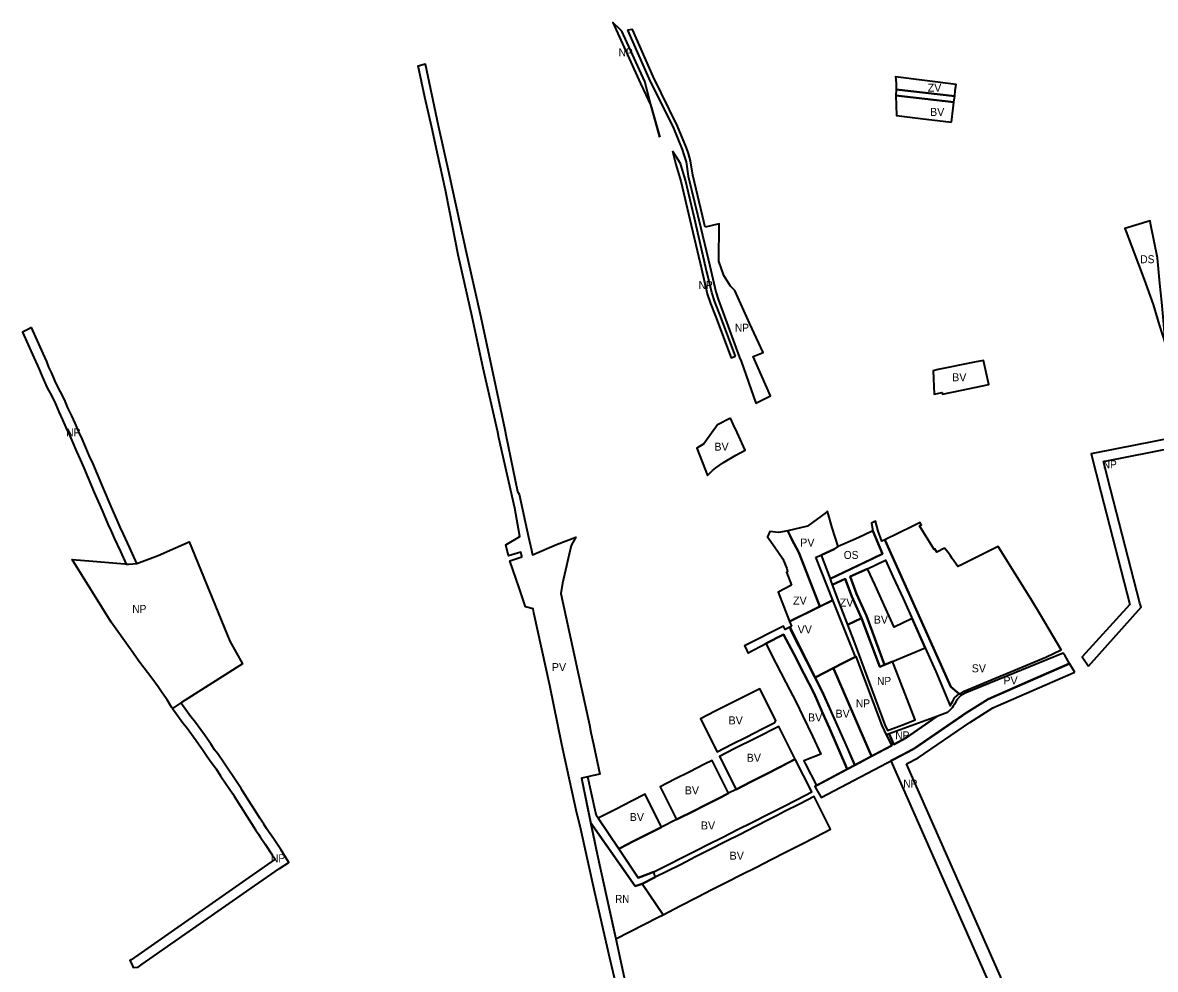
# Model space of a CAD drawing. Extents: x -650276 to -642489, y -1074311 to -1066658.
# Drawn here: x -649558 to -647860, y -1068079 to -1066658 of the extents above; entities that cross this region are included whole.
import ezdxf

# ---------------------------------------------------------------- set-up
doc = ezdxf.new("R2010")
doc.units = 0
doc.header["$LTSCALE"] = 4.8
for name, color, linetype, lineweight in [('15', 7, 'Continuous', 35), ('18', 7, 'Continuous', 35), ('24', 7, 'Continuous', 35), ('3', 7, 'Continuous', 35), ('40', 7, 'Continuous', 35), ('45', 7, 'Continuous', 35), ('48', 7, 'Continuous', 35), ('7', 7, 'Continuous', 35), ('9', 7, 'Continuous', 35)]:
    doc.layers.add(name, color=color, linetype=linetype, lineweight=lineweight)
doc.layers.add('62', color=7, linetype='Continuous')
doc.layers.add('63', color=7, linetype='Continuous')

msp = doc.modelspace()

# ---------------------------------------------------------------- linework, layer by layer
at = {"layer": '15'}
for points in [[(-648662.71, -1068124.76), (-648677.61, -1068061.74), (-648700.16, -1067963.42), (-648722.09, -1067863.84), (-648727.05, -1067844.33), (-648738.7, -1067792.04), (-648749.97, -1067741.49), (-648767.84, -1067652.98), (-648791.68, -1067543.78), (-648792.97, -1067537.86), (-648804.08, -1067534.88), (-648813.94, -1067506.27), (-648827.86, -1067465.86), (-648809.65, -1067459.77), (-648809.97, -1067458.52), (-648811.21, -1067453.52), (-648811.4, -1067452.79), (-648829.54, -1067458.42), (-648834.01, -1067441.81), (-648812.91, -1067429.16), (-648820.39, -1067386.83), (-648844.16, -1067281.37), (-648845.94, -1067272.85), (-648867.82, -1067176.66), (-648884.26, -1067099.63), (-648899.1, -1067033.34), (-648905.06, -1067006.7), (-648917.76, -1066942.65), (-648924.32, -1066909.55), (-648936.7, -1066852.52), (-648944.75, -1066815.41), (-648955.15, -1066770.11), (-648965.39, -1066723.15), (-648959.88, -1066721.59), (-648954.86, -1066720.16), (-648935.19, -1066812.53), (-648918.27, -1066888.41), (-648914.11, -1066907.05), (-648893.02, -1067002.5), (-648872.31, -1067095.5), (-648851.87, -1067191.04), (-648835.29, -1067268.93), (-648833.66, -1067276.77), (-648816.06, -1067361.71), (-648813.81, -1067365.91), (-648799.58, -1067430.4), (-648796.8, -1067443.1), (-648795.88, -1067447.21), (-648794.7, -1067452.46), (-648793.71, -1067456.88), (-648757.97, -1067441.51), (-648728.95, -1067430.33), (-648735.59, -1067442.88), (-648748.53, -1067499.3), (-648751.29, -1067514.57), (-648731.06, -1067607.06), (-648725.8, -1067632.36), (-648720.1, -1067657.12), (-648708.26, -1067712.07), (-648706.08, -1067723.56), (-648702.33, -1067740.84), (-648692.53, -1067785.79), (-648704.614, -1067788.491), (-648710.961, -1067789.906), (-648720.34, -1067792), (-648696.93, -1067905.76), (-648672.31, -1068017.25), (-648668.92, -1068032.96), (-648651.89, -1068111.95)], [(-648710.961, -1067789.906), (-648720.34, -1067792), (-648706.687, -1067858.345), (-648640, -1067954)], [(-648695.27, -1067852.04), (-648697.7, -1067848.43), (-648699.621, -1067840.06), (-648699.593, -1067840.046), (-648710.96, -1067789.91)], [(-648611.61, -1067932.63), (-648620.658, -1067935.93), (-648635.249, -1067941.252), (-648664.41, -1067897.91), (-648695.27, -1067852.04)], [(-648640, -1067954), (-648629.22, -1067950.214), (-648609.91, -1067940.58), (-648611.61, -1067932.63)]]:
    msp.add_lwpolyline(points, dxfattribs=at)
for points in [[(-648161.58, -1066777.41), (-648160.51, -1066768.4), (-648248.43, -1066758.34), (-648248.77, -1066767.43)], [(-648369.01, -1067460.52), (-648361, -1067457.36), (-648341.15, -1067448.14), (-648335.38, -1067444.07), (-648344.41, -1067416.04), (-648349.67, -1067396.88), (-648351.06, -1067391.62), (-648352.16, -1067392.42), (-648353.35, -1067393.29), (-648381.48, -1067413.68), (-648410.92, -1067420.63), (-648409.61, -1067423.44), (-648404.29, -1067434.9), (-648394.92, -1067452.23), (-648393.17, -1067455.88), (-648362.585, -1067534.205), (-648343.41, -1067524.81), (-648369.01, -1067460.52)], [(-648237.81, -1067522.42), (-648204.88, -1067596.54), (-648198.39, -1067610.97), (-648193.8, -1067621), (-648189.03, -1067631.71), (-648167.48, -1067683.45), (-648164.79, -1067678.96), (-648163.11, -1067676.17), (-648160.68, -1067671.55), (-648153.98, -1067665.43), (-648166.173, -1067654.853), (-648240.51, -1067489.9), (-648265.197, -1067434.03), (-648265.197, -1067434.03), (-648270.02, -1067436.37), (-648275.41, -1067421.3), (-648279.24, -1067406.38), (-648285.08, -1067409.24), (-648283.21, -1067420.88), (-648268.67, -1067455.43), (-648297.915, -1067469.319), (-648326.09, -1067482.7), (-648347.51, -1067492.87), (-648346.27, -1067496.14), (-648344.186, -1067501.627), (-648324.735, -1067492.8), (-648314.647, -1067519.171), (-648300.258, -1067551.772), (-648299.23, -1067554.52), (-648272.941, -1067624.811), (-648265.601, -1067621.762), (-648292.991, -1067548.356), (-648307.57, -1067515.44), (-648317.435, -1067489.488), (-648291.172, -1067477.571), (-648264.34, -1067464.83), (-648253.1, -1067489.23)], [(-648359.6, -1067691.58), (-648348.55, -1067716.71), (-648337.32, -1067742.59), (-648326, -1067769), (-648321.623, -1067778.399), (-648310.511, -1067772.476), (-648323.178, -1067741.953), (-648359.213, -1067661.956), (-648405.054, -1067571.837), (-648408.002, -1067565.219), (-648414.73, -1067568.8), (-648417.19, -1067564.02), (-648475.78, -1067593.11), (-648473.34, -1067598.06), (-648470.57, -1067603.69), (-648470.47, -1067603.64), (-648443.83, -1067589.92), (-648417.12, -1067576.17), (-648402.02, -1067605.49), (-648386.91, -1067634.83), (-648371.34, -1067665.08)], [(-647988.235, -1067619.912), (-647995.04, -1067608.56), (-647997.68, -1067604.11), (-648144.83, -1067664.48), (-648151.6, -1067668.12), (-648157.2, -1067674.32), (-648161, -1067680.96), (-648162.69, -1067684), (-648164.09, -1067686.51), (-648171.21, -1067693.37), (-648187.139, -1067699.179), (-648233.264, -1067731.288), (-648251.711, -1067741.124), (-648258.96, -1067725.37), (-648262.632, -1067726.711), (-648255.016, -1067742.886), (-648319.983, -1067777.526), (-648370.113, -1067804.22), (-648360.993, -1067821.027), (-648222.872, -1067748.412), (-648146.127, -1067695.8), (-648110.36, -1067673.133), (-647988.052, -1067619.624)]]:
    msp.add_lwpolyline(points, close=True, dxfattribs=at)
at = {"layer": '18'}
msp.add_lwpolyline([(-648153.98, -1067665.43), (-648149.933, -1067663.646), (-648146.21, -1067661.3), (-648023.96, -1067610.13), (-648000.63, -1067599.14), (-648031.77, -1067546.6), (-648045.04, -1067525.15), (-648076.32, -1067474.6), (-648081.31, -1067466.54), (-648095.28, -1067444.06), (-648133.56, -1067463.2), (-648150.46, -1067471.66), (-648155.85, -1067474.35), (-648164.24, -1067462.15), (-648166.97, -1067458.18), (-648170.38, -1067453.23), (-648175.94, -1067446.89), (-648187.44, -1067452.8), (-648190.23, -1067447.83), (-648191.46, -1067448.59), (-648213.34, -1067413.46), (-648210.48, -1067411.68), (-648211.08, -1067410.6), (-648212.32, -1067408.39), (-648224.19, -1067414.14), (-648265.197, -1067434.03), (-648240.51, -1067489.9), (-648240.51, -1067489.9), (-648166.173, -1067654.853)], close=True, dxfattribs=at)
at = {"layer": '24'}
msp.add_lwpolyline([(-647876.57, -1067043.5), (-647863.04, -1067081.36), (-647853.65, -1067111.91), (-647844.3, -1067141.25), (-647847.09, -1067110.58), (-647850.07, -1067077.71), (-647852.63, -1067049.52), (-647856.11, -1067011.21), (-647866.14, -1066961.98), (-647867.46, -1066955.52), (-647905.28, -1066967.07), (-647903.5, -1066972.05)], close=True, dxfattribs=at)
at = {"layer": '3'}
for points in [[(-648165.33, -1066807.74), (-648162.8, -1066786.8), (-648161.58, -1066777.41), (-648248.77, -1066767.43), (-648247.78, -1066797.53), (-648211.58, -1066802.18)], [(-648185.185, -1067178.687), (-648193.02, -1067180.66), (-648191.44, -1067215.62), (-648179.42, -1067213.37), (-648179, -1067215.71), (-648152.5, -1067210.23), (-648109.1, -1067201.21), (-648117.562, -1067165.197), (-648131.01, -1067167.84)], [(-648496.55, -1067251.53), (-648516.47, -1067261.54), (-648536.84, -1067290.29), (-648547.17, -1067296.68), (-648531.51, -1067337.57), (-648523.55, -1067330.33), (-648518.55, -1067326.3), (-648507.25, -1067318.35), (-648488.66, -1067307.11), (-648474.69, -1067299.66), (-648486.79, -1067273.26), (-648492.62, -1067260.53)], [(-648263.7, -1067537.93), (-648279.86, -1067502.11), (-648291.17, -1067477.57), (-648317.435, -1067489.488), (-648307.57, -1067515.44), (-648292.991, -1067548.356), (-648265.601, -1067621.762), (-648254.04, -1067616.96), (-648254.04, -1067616.96), (-648204.88, -1067596.54), (-648224.16, -1067552.55), (-648251.33, -1067565.28)], [(-648397.98, -1067678.79), (-648388.526, -1067698.603), (-648373.99, -1067728.95), (-648361.08, -1067755.88), (-648387.04, -1067765.67), (-648384.25, -1067771.07), (-648367.811, -1067802.994), (-648321.623, -1067778.399), (-648326, -1067769), (-648337.32, -1067742.59), (-648348.55, -1067716.71), (-648359.6, -1067691.58), (-648371.34, -1067665.08), (-648386.91, -1067634.83), (-648402.02, -1067605.49), (-648417.12, -1067576.17), (-648443.83, -1067589.92), (-648428.7, -1067619.24), (-648413.57, -1067648.57)], [(-648342.697, -1067626.806), (-648369.949, -1067640.851), (-648359.213, -1067661.956), (-648310.511, -1067772.476), (-648285.254, -1067759.008), (-648296.891, -1067732.172), (-648342.023, -1067628.096)], [(-648519.63, -1067691.58), (-648541.86, -1067702.86), (-648516.73, -1067752.57), (-648494.84, -1067741.06), (-648472.5, -1067729.76), (-648450.23, -1067718.32), (-648430.17, -1067708.33), (-648428.67, -1067705.52), (-648452.72, -1067657.62)], [(-648491.14, -1067748.02), (-648513.23, -1067759.38), (-648488.49, -1067808.76), (-648466.36, -1067797.5), (-648455.32, -1067791.85), (-648444.28, -1067786.19), (-648421.84, -1067774.66), (-648410.78, -1067768.98), (-648399.64, -1067763.26), (-648424.14, -1067714.34), (-648435.34, -1067720.01), (-648446.58, -1067725.71), (-648468.97, -1067736.91), (-648480.06, -1067742.47)], [(-648577.78, -1067854.07), (-648571.69, -1067851.06), (-648555.32, -1067842.99), (-648532.98, -1067831.54), (-648510.82, -1067820.19), (-648499.7, -1067814.37), (-648524.44, -1067765.11), (-648535.61, -1067770.85), (-648557.84, -1067782.26), (-648580.14, -1067793.61), (-648602.3, -1067804.83)], [(-648644.095, -1067887.6), (-648620.51, -1067875.63), (-648600.14, -1067865.29), (-648624.76, -1067816.11), (-648645.11, -1067826.48), (-648668.085, -1067838.186), (-648675.26, -1067841.84), (-648695.27, -1067852.04), (-648664.41, -1067897.91), (-648650.68, -1067890.94)]]:
    msp.add_lwpolyline(points, close=True, dxfattribs=at)
for points in [[(-648611.61, -1067932.63), (-648611.61, -1067932.63), (-648547.09, -1067899.87), (-648530.81, -1067891.61), (-648508.22, -1067880.38), (-648486.09, -1067868.98), (-648463.91, -1067857.74), (-648441.47, -1067846.37), (-648419.44, -1067835.3), (-648397.04, -1067823.85), (-648374.84, -1067812.43), (-648399.64, -1067763.26), (-648421.84, -1067774.66)], [(-648421.84, -1067774.66), (-648444.28, -1067786.19), (-648455.32, -1067791.85), (-648466.36, -1067797.5), (-648488.49, -1067808.76)], [(-648572.5, -1067983.59), (-648546.76, -1067970.44), (-648524.72, -1067958.93), (-648502.59, -1067948), (-648480.12, -1067936.55), (-648457.87, -1067925.4), (-648435.55, -1067913.84), (-648413.41, -1067902.53), (-648402.29, -1067897.02), (-648391.08, -1067891.24), (-648368.78, -1067879.75), (-648346.57, -1067868.56), (-648371.27, -1067819.47), (-648393.35, -1067830.81), (-648415.69, -1067841.98), (-648426.65, -1067847.64), (-648437.89, -1067853.4), (-648460.33, -1067864.88), (-648482.5, -1067876.22), (-648504.92, -1067887.52), (-648527.33, -1067898.74), (-648549.44, -1067910.07), (-648571.88, -1067921.71), (-648591.04, -1067931.62), (-648609.91, -1067940.58)], [(-648488.49, -1067808.76), (-648499.7, -1067814.37), (-648510.82, -1067820.19), (-648532.98, -1067831.54), (-648555.32, -1067842.99), (-648571.69, -1067851.06)], [(-648571.69, -1067851.06), (-648577.78, -1067854.07), (-648600.14, -1067865.29)], [(-648600.14, -1067865.29), (-648620.51, -1067875.63), (-648644.095, -1067887.6)], [(-648644.095, -1067887.6), (-648650.68, -1067890.94), (-648664.41, -1067897.91), (-648635.249, -1067941.252), (-648620.658, -1067935.93), (-648611.61, -1067932.63)], [(-648609.91, -1067940.58), (-648629.22, -1067950.214), (-648597.93, -1067996.72), (-648572.5, -1067983.59)]]:
    msp.add_lwpolyline(points, dxfattribs=at)
at = {"layer": '40'}
for points in [[(-648160.51, -1066768.4), (-648159.66, -1066759.8), (-648158.49, -1066750.93), (-648249.44, -1066739.8), (-648248.34, -1066749.33), (-648248.43, -1066758.34)], [(-648405.27, -1067502.27), (-648425.5, -1067512.73), (-648408.26, -1067556.58), (-648362.585, -1067534.205), (-648393.17, -1067455.88), (-648394.92, -1067452.23), (-648404.29, -1067434.9), (-648410.92, -1067420.63), (-648425, -1067423.05), (-648437.75, -1067421.99), (-648441.48, -1067429.63), (-648430.4, -1067445.51), (-648418.3, -1067462.86), (-648412.46, -1067477.42), (-648411.25, -1067481.73), (-648412.89, -1067482.55)], [(-648324.735, -1067492.8), (-648344.186, -1067501.627), (-648334.09, -1067528.2), (-648321.36, -1067561.69), (-648300.258, -1067551.772), (-648314.647, -1067519.171)]]:
    msp.add_lwpolyline(points, close=True, dxfattribs=at)
for points in [[(-648314.647, -1067519.171), (-648324.735, -1067492.8), (-648344.186, -1067501.627)], [(-648344.186, -1067501.627), (-648334.09, -1067528.2), (-648321.36, -1067561.69)], [(-648321.36, -1067561.69), (-648300.258, -1067551.772), (-648314.647, -1067519.171)]]:
    msp.add_lwpolyline(points, dxfattribs=at)
at = {"layer": '45'}
msp.add_lwpolyline([(-648405.41, -1067563.84), (-648408.002, -1067565.219), (-648369.949, -1067640.851), (-648342.697, -1067626.806), (-648328.54, -1067619.51), (-648309.522, -1067609.713), (-648317.43, -1067590), (-648343.41, -1067524.81), (-648408.26, -1067556.58)], close=True, dxfattribs=at)
at = {"layer": '48'}
for points in [[(-648602.97, -1066830.11), (-648616.86, -1066779.79), (-648625.44, -1066746.45), (-648659.95, -1066670.89), (-648662.46, -1066668.53), (-648673.407, -1066658.275), (-648631.791, -1066749.394)], [(-648534.701, -1066965.077), (-648538.812, -1066947.891), (-648553.323, -1066887.238), (-648556.637, -1066865.397), (-648559.94, -1066854.66), (-648562.542, -1066846.219), (-648576.145, -1066813.802), (-648612.763, -1066739.165), (-648643.925, -1066668.483), (-648651.042, -1066669.551), (-648651.1, -1066669.56)], [(-648651.1, -1066669.56), (-648619.11, -1066742.12), (-648582.52, -1066816.7)], [(-648631.791, -1066749.394), (-648616.104, -1066782.727), (-648602.97, -1066830.11)], [(-648582.52, -1066816.7), (-648569.13, -1066848.61), (-648566.63, -1066856.72), (-648563.48, -1066866.96), (-648560.2, -1066888.58), (-648541.521, -1066966.657), (-648541.52, -1066966.657)], [(-648571.96, -1066869.37), (-648577.99, -1066860.17), (-648583.94, -1066851.11)], [(-648583.94, -1066851.11), (-648578.702, -1066871.259), (-648571.167, -1066896.326), (-648557.816, -1066953.444)], [(-648489.1, -1067158.84), (-648512.95, -1067095.97), (-648520.4, -1067077.42), (-648524.93, -1067063.35), (-648533.66, -1067026), (-648551, -1066951.85), (-648564.4, -1066894.52), (-648571.96, -1066869.37)], [(-648557.816, -1066953.444), (-648540.476, -1067027.594), (-648531.681, -1067065.222)], [(-648541.52, -1066966.657), (-648528.01, -1067023.13), (-648518.72, -1067061.99), (-648514.86, -1067074.83), (-648507.88, -1067093.9), (-648483.31, -1067160.63), (-648480.57, -1067166.13), (-648458.73, -1067229.1), (-648449.03, -1067224.14), (-648437.02, -1067217.99), (-648462.97, -1067159.24), (-648447.66, -1067153.25), (-648467.56, -1067110.02), (-648490.23, -1067060.06), (-648496.87, -1067053.5), (-648506.78, -1067037.81), (-648514.38, -1067016.2), (-648513.842, -1066960.243), (-648534.701, -1066965.077)], [(-648531.681, -1067065.222), (-648526.988, -1067079.8), (-648519.471, -1067098.516), (-648495.644, -1067161.326), (-648489.1, -1067158.84)], [(-647882.66, -1067529.231), (-647926.759, -1067358.379), (-647937.355, -1067316.774), (-647828.376, -1067295.406), (-647828.104, -1067295.352), (-647831.28, -1067280.69), (-647948.488, -1067303.671)], [(-647948.488, -1067303.671), (-647955.805, -1067305.106), (-647941.289, -1067362.104)], [(-647941.289, -1067362.104), (-647897.637, -1067531.223), (-647969.29, -1067609.79), (-647959.832, -1067623.65)], [(-647959.832, -1067623.65), (-647881.085, -1067535.333), (-647882.66, -1067529.231)], [(-648254.04, -1067616.96), (-648272.941, -1067624.811), (-648300.258, -1067551.772), (-648321.36, -1067561.69)], [(-648321.36, -1067561.69), (-648311.95, -1067586.45), (-648265.08, -1067712.06)], [(-648265.08, -1067712.06), (-648261.25, -1067720.39), (-648235.78, -1067710.79), (-648219.86, -1067704.42), (-648247.53, -1067633.53), (-648254.04, -1067616.96)], [(-648095.475, -1067682.994), (-647983.06, -1067633.813), (-647980.561, -1067632.719)], [(-647980.561, -1067632.719), (-647982.95, -1067628.73), (-647988.334, -1067619.747), (-648046.773, -1067645.314)], [(-648046.773, -1067645.314), (-648110.36, -1067673.133), (-648146.127, -1067695.8), (-648146.146, -1067695.813), (-648149.529, -1067698.132), (-648222.53, -1067748.178)], [(-648232.676, -1067770.513), (-648215.115, -1067761.28), (-648137.869, -1067708.325), (-648114.323, -1067693.403), (-648103.298, -1067686.416), (-648095.475, -1067682.994)], [(-648222.53, -1067748.178), (-648222.872, -1067748.412), (-648238.748, -1067756.759)], [(-648238.748, -1067756.759), (-648256.499, -1067766.091), (-648079.002, -1068168.139)], [(-648079.002, -1068168.139), (-648061.329, -1068158.649), (-648232.676, -1067770.513)]]:
    msp.add_lwpolyline(points, dxfattribs=at)
for points in [[(-649545.203, -1067115.647), (-649549.7, -1067118.05), (-649558.469, -1067122.73), (-649541.537, -1067160.722), (-649536.075, -1067172.622), (-649532.831, -1067180.855), (-649529.013, -1067189.389), (-649521.663, -1067206.124), (-649514.869, -1067218.957), (-649509.44, -1067230.141), (-649504.224, -1067242.225), (-649498.572, -1067254.427), (-649493.526, -1067265.611), (-649487.812, -1067278.312), (-649482.963, -1067288.934), (-649477.677, -1067301.655), (-649472.327, -1067313.644), (-649466.703, -1067326.24), (-649451.059, -1067363.074), (-649439.265, -1067390.397), (-649430.531, -1067410.689), (-649425.804, -1067421.21), (-649421.071, -1067431.944), (-649411.913, -1067451.746), (-649403.34, -1067470.579), (-649399.39, -1067470.93), (-649387.4, -1067469.98), (-649387.17, -1067469.894), (-649398.28, -1067445.49), (-649407.4, -1067425.77), (-649412.1, -1067415.11), (-649416.8, -1067404.65), (-649425.49, -1067384.46), (-649437.27, -1067357.17), (-649452.95, -1067320.25), (-649458.63, -1067307.53), (-649463.9, -1067295.72), (-649469.21, -1067282.94), (-649474.15, -1067272.12), (-649479.85, -1067259.45), (-649484.93, -1067248.19), (-649490.53, -1067236.1), (-649495.8, -1067223.89), (-649501.49, -1067212.17), (-649508.15, -1067199.59), (-649515.3, -1067183.31), (-649519, -1067175.04), (-649522.27, -1067166.74), (-649527.87, -1067154.54)], [(-649333.74, -1067687.4), (-649335.26, -1067685.21), (-649341.81, -1067674.33), (-649349.12, -1067663.84), (-649355.46, -1067654.85), (-649364.69, -1067641.98), (-649382.53, -1067618.33), (-649391.04, -1067606.27), (-649393.23, -1067603.28), (-649425.69, -1067557.7), (-649484.28, -1067463.88), (-649453.39, -1067466.13), (-649399.39, -1067470.93), (-649387.4, -1067469.98), (-649355.44, -1067457.94), (-649329.068, -1067446.175), (-649308.75, -1067437.11), (-649247.518, -1067586.255), (-649228.52, -1067620.294), (-649320.47, -1067678.44)], [(-648342.023, -1067628.096), (-648296.891, -1067732.172), (-648285.254, -1067759.008), (-648255.016, -1067742.886), (-648265.614, -1067720.378), (-648269.27, -1067712.6), (-648308.43, -1067609.15), (-648328.54, -1067619.51), (-648342.697, -1067626.806)], [(-649321.3, -1067679), (-649333.74, -1067687.4), (-649328.34, -1067694.79), (-649317.99, -1067708.85), (-649312.91, -1067715.45), (-649298.02, -1067735.58), (-649290.15, -1067746.92), (-649288.63, -1067748.97), (-649282.85, -1067757.79), (-649278.14, -1067764.31), (-649268.46, -1067777.97), (-649261.48, -1067788.47), (-649253.98, -1067799.2), (-649243.37, -1067815.17), (-649241.28, -1067818.7), (-649228.27, -1067839.26), (-649222.11, -1067849.12), (-649215.32, -1067859.99), (-649209.39, -1067869.34), (-649204.87, -1067875.85), (-649202.02, -1067880.07), (-649194.77, -1067890.67), (-649184, -1067906.88), (-649179.96, -1067913.35), (-649219.088, -1067940.964), (-649395.729, -1068064.23), (-649397.466, -1068065.442), (-649394.83, -1068071.05), (-649392.88, -1068075.9), (-649385.41, -1068075.32), (-649379.295, -1068071.053), (-649210.54, -1067953.29), (-649172.99, -1067927.41), (-649159.179, -1067918.309), (-649171.389, -1067898.756), (-649182.332, -1067882.285), (-649189.614, -1067871.638), (-649192.493, -1067867.375), (-649196.89, -1067861.042), (-649202.625, -1067852), (-649209.388, -1067841.173), (-649215.571, -1067831.276), (-649228.486, -1067810.867), (-649230.661, -1067807.193), (-649241.584, -1067790.752), (-649249.085, -1067780.02), (-649256.092, -1067769.48), (-649265.941, -1067755.582), (-649270.491, -1067749.283), (-649276.322, -1067740.385), (-649277.961, -1067738.175), (-649285.826, -1067726.842), (-649300.936, -1067706.414), (-649306.005, -1067699.828), (-649316.244, -1067685.919)], [(-648258.96, -1067725.37), (-648251.711, -1067741.124), (-648233.264, -1067731.288), (-648187.139, -1067699.179)]]:
    msp.add_lwpolyline(points, close=True, dxfattribs=at)
at = {"layer": '7'}
msp.add_lwpolyline([(-648640, -1067954), (-648706.687, -1067858.345), (-648696.93, -1067905.76), (-648668.92, -1068032.96), (-648605.323, -1068000.463), (-648597.93, -1067996.72), (-648629.22, -1067950.214)], close=True, dxfattribs=at)
at = {"layer": '9'}
msp.add_lwpolyline([(-648268.67, -1067455.43), (-648283.21, -1067420.88), (-648295.66, -1067426.76), (-648309.57, -1067433.34), (-648335.38, -1067444.07), (-648341.15, -1067448.14), (-648361, -1067457.36), (-648347.51, -1067492.87), (-648326.09, -1067482.7)], close=True, dxfattribs=at)

# ---------------------------------------------------------------- texts
at = {"layer": '62'}
for s, width, p in [('NP', 0.95, (-648664.583, -1066709.041)), ('NP', 0.95, (-648544.583, -1067058.041)), ('NP', 0.95, (-648490.15, -1067121.972)), ('NP', 0.95, (-649492.985, -1067278.967)), ('NP', 0.95, (-647938.583, -1067327.041)), ('NP', 0.95, (-649393.985, -1067543.967)), ('NP', 0.95, (-648277.019, -1067651.94)), ('NP', 0.95, (-648308.631, -1067685.579)), ('NP', 0.95, (-648237.583, -1067806.041)), ('NP', 0.95, (-649185.985, -1067917.967)), ('RN', 0.9, (-648669.473, -1067979.058))]:
    msp.add_text(s, height=12, dxfattribs=dict(at, width=width)).set_placement(p)
for s, p in [('ZV', (-648201.026, -1066761.906)), ('BV', (-648197.475, -1066798.284)), ('BV', (-648164.386, -1067196.331)), ('BV', (-648520.956, -1067300.498)), ('PV', (-648392.213, -1067444.317)), ('ZV', (-648402.918, -1067531.307)), ('ZV', (-648332.918, -1067534.307)), ('VV', (-648396.075, -1067574.614)), ('PV', (-648764.767, -1067631.209)), ('SV', (-648135.028, -1067633.035)), ('PV', (-648087.517, -1067651.275)), ('BV', (-648499.724, -1067711.153)), ('BV', (-648380.551, -1067706.775)), ('BV', (-648339.301, -1067701.063)), ('BV', (-648472.48, -1067767.243)), ('BV', (-648565.429, -1067816.121)), ('BV', (-648647.961, -1067856.185)), ('BV', (-648541.281, -1067868.87)), ('BV', (-648498.112, -1067914.191))]:
    msp.add_text(s, height=12, dxfattribs=at).set_placement(p)
at = {"layer": '63', "width": 0.95}
for s, p in [('DS', (-647882.118, -1067019.225)), ('OS', (-648326.942, -1067462.923)), ('NP', (-648249.631, -1067733.579))]:
    msp.add_text(s, height=12, dxfattribs=at).set_placement(p)
at = {"layer": '63'}
msp.add_text('BV', height=12, dxfattribs=at).set_placement((-648281.942, -1067559.923))

doc.saveas('drawing.dxf')
